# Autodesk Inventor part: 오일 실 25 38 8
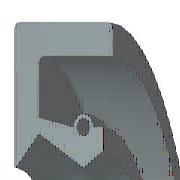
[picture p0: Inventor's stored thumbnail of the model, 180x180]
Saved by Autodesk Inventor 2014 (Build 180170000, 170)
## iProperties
Created: 2012-02
Part Number: 오일 실 25 38 8
Material: 고무
Description: 오일-실
Document SubType Name: Modeling
Standard: KS B 2804
Designer: mduedu
Standards Organization: KS
Language: ko-KR
Size Designation: D - 25 38 8
Categories: <MemberInstance><Categories><Category DisplayName="샤프트 부품" InternalName="7f7aeb1f-a693-4053-b835-cee3144e0d98" Mnemonic="SHFT"><Category DisplayName="실링" Intern
Density: 0.93 g/cm^3
Appearance: Rubber - Black - Version 1.1
IsCustomPart: 1
Author: mduedu
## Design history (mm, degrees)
revolve "본체" stored, may be unused: angle "d17" = 90 deg
revolve "스프링1" stored, may be unused: angle "d18" = 90 deg
body "Solid1"
sketch "스케치1"
  geometry: L1 (0, 19)-(8, 19); L2 (8, 17.25)-(1.75, 17.25); L3 (1.75, 14.25)-(4.9, 12.5); L4 (4.9, 12.5)-(0, 12.5); L5 (0, 0)-(9.586, 0) reference; L6 (4.9, 12.5)-(6.3, 13.375); L7 (0, 18)-(0, -3) reference; L8 (-1.941, 0)-(11.507, 0) reference; L9 (4.2, 14.6)-(1.75, 15.21); L10 (1.75, 15.21)-(1.75, 17.25); L11 (0, 19)-(0, 12.588); L12 (4.9, 12.5)-(0, 12.5); L13 (1.75, 14.25)-(0.152, 12.528); L14 (8, 19)-(8, 17.25); L15 (5.6, 14.6)-(6.3, 14.6); L16 (6.3, 14.6)-(6.3, 13.375); C1 r 0.455 at (4.9, 14.6); A1 r 0.7 centre (4.9, 14.6) between (5.6, 14.6) and (4.2, 14.6); A2 r 0.088 centre (0.087, 12.588) between (0, 12.588) and (0.152, 12.528); 1 further point
  constraints: 28 end point, 5 horizontal alignment, 5 point on line, 4 point on circle, 4 vertical alignment, 3 centre point, 3 tangent, 2 collinear, 2 horizontal, 2 perpendicular, 1 coincident, 1 parallel
  dimensions: "d0" = 38 diameter of L1 L5 (= SD2); "d1" = 1.75 distance of L1.end L2.start (= SD); "d2" = 0.91 diameter of C1 (= SPDI); "d3" = 1.4 diameter of A1 (= SPDA); "d4" = 25 diameter of L3.end L5 (= NND); "d5" = 28.5 diameter of L3.start L5 (= TKDM); "d7" = 30.42 diameter of L9.end L5 (= TKDM + 0.24 x SWDT); "d8" = 1.75 distance between parallel lines of L11 L10 (= SD); "d9" = 4.9 distance from line of L11 C1.centre (= SPDST); "d10" = 29.2 diameter of C1.centre L5 (= HLDM); "d11" = 0.0875 radius of A2 (= 0.25 x LAB); "d12" = 6.3 distance between parallel lines of L11 L16 (= SDI); "d13" = 26.75 diameter of L6.end L5 (= ABDM); "d14" = 8 distance from line of L11 L1.end (= SWDT)
fillet "모깎기1" dims "d6" = 0.3 (= RR)
other parameters: "SD2" = 38 [user parameter; used in 1 equation term], "SWDT" = 8 [user parameter; used in 2 equation terms], "RR" = 0.3 [user parameter; used in 1 equation term], "SD" = 1.75 [user parameter; used in 2 equation terms], "NND" = 25 [user parameter; used in 1 equation term], "SPDA" = 1.4 [user parameter; used in 1 equation term], "SPDI" = 0.91 [user parameter; used in 1 equation term], "TKDM" = 28.5 [user parameter; used in 2 equation terms], "HLDM" = 29.2 [user parameter; used in 1 equation term], "ABDM" = 26.75 [user parameter; used in 1 equation term], "SDI" = 6.3 [user parameter; used in 1 equation term], "SPDST" = 4.9 [user parameter; used in 1 equation term], "LAB" = 0.35 [user parameter; used in 1 equation term], "d15" = 0, "d16" = 0, "d19" = 0
